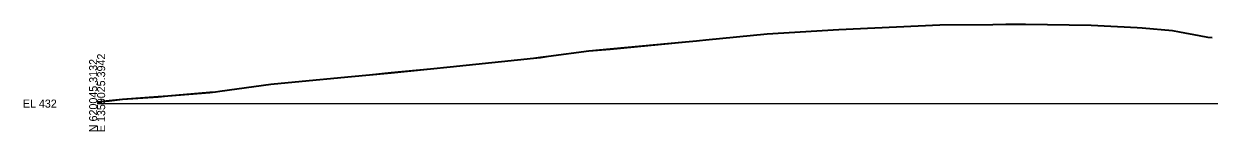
# Model space of a CAD drawing. Extents: x -26 to 803, y -27 to 3586.
# Drawn here: x -25.7 to 389.1, y 2990.3 to 3027.9 of the extents above; entities that cross this region are included whole.
import ezdxf

# ---------------------------------------------------------------- set-up
doc = ezdxf.new("R2010")
doc.units = 0
for name, color, linetype in [('DESIGN - SHEET - Light Grid', 7, 'Continuous'), ('SURVEY - GROUND - Bottom of Topsoil Layer', 7, 'Continuous'), ('SURVEY - GROUND - Top of Ground', 7, 'Continuous')]:
    doc.layers.add(name, color=color, linetype=linetype)

msp = doc.modelspace()

# ---------------------------------------------------------------- linework, layer by layer
at = {"layer": 'DESIGN - SHEET - Light Grid'}
msp.add_line((0, 3000), (400, 3000), dxfattribs=at)
at = {"layer": 'SURVEY - GROUND - Bottom of Topsoil Layer'}
for p, q in [((212.92, 3022.16), (234.42, 3024.27)), ((234.42, 3024.27), (259.53, 3025.76)), ((259.53, 3025.76), (272.12, 3026.35)), ((272.12, 3026.35), (294.85, 3027.45)), ((294.85, 3027.45), (313.39, 3027.55)), ((313.39, 3027.55), (317.86, 3027.61)), ((317.86, 3027.61), (320.11, 3027.67)), ((320.11, 3027.67), (321.84, 3027.69)), ((321.84, 3027.69), (324.75, 3027.61)), ((324.75, 3027.61), (347.82, 3027.26)), ((347.82, 3027.26), (363.88, 3026.5)), ((363.88, 3026.5), (365.66, 3026.4)), ((365.66, 3026.4), (376.24, 3025.47)), ((376.24, 3025.47), (378.72, 3025.01)), ((378.72, 3025.01), (385.5, 3023.66)), ((179.53, 3018.97), (205.87, 3021.45)), ((205.87, 3021.45), (209.66, 3021.81)), ((209.66, 3021.81), (210.76, 3021.92)), ((210.76, 3021.92), (212.92, 3022.16)), ((385.5, 3023.66), (388.58, 3023.15)), ((388.58, 3023.15), (390.12, 3022.95)), ((147.05, 3015.17), (152.71, 3015.79)), ((152.71, 3015.79), (155.06, 3016.06)), ((155.06, 3016.06), (157.88, 3016.43)), ((157.88, 3016.43), (172.02, 3018.29)), ((172.02, 3018.29), (179.53, 3018.97)), ((102.83, 3010.69), (116.65, 3012.03)), ((116.65, 3012.03), (123.48, 3012.72)), ((123.48, 3012.72), (147.05, 3015.17)), ((60.81, 3006.62), (69.23, 3007.47)), ((69.23, 3007.47), (88.95, 3009.34)), ((88.95, 3009.34), (95.26, 3009.91)), ((95.26, 3009.91), (102.83, 3010.69)), ((24.74, 3002.62), (39.41, 3003.81)), ((39.41, 3003.81), (41.46, 3004)), ((41.46, 3004), (42.9, 3004.2)), ((42.9, 3004.2), (60.81, 3006.62)), ((0, 3000.48), (4.26, 3000.89)), ((4.26, 3000.89), (8.89, 3001.41)), ((8.89, 3001.41), (21.33, 3002.3)), ((21.33, 3002.3), (24.74, 3002.62))]:
    msp.add_line(p, q, dxfattribs=at)
at = {"layer": 'SURVEY - GROUND - Top of Ground'}
msp.add_lwpolyline([(0, 3000.73), (4.26, 3001.14), (8.89, 3001.66), (21.33, 3002.55), (24.74, 3002.87), (39.41, 3004.06), (41.46, 3004.25), (42.9, 3004.45), (60.81, 3006.87), (69.23, 3007.72), (88.95, 3009.59), (95.26, 3010.16), (102.83, 3010.94), (116.65, 3012.28), (123.48, 3012.97), (147.05, 3015.42), (152.71, 3016.04), (155.06, 3016.31), (157.88, 3016.68), (172.02, 3018.54), (179.53, 3019.22), (205.87, 3021.7), (209.66, 3022.06), (210.76, 3022.17), (212.92, 3022.41), (234.42, 3024.52), (259.53, 3026.01), (272.12, 3026.6), (294.85, 3027.7), (313.39, 3027.8), (317.86, 3027.86), (320.11, 3027.92), (321.84, 3027.94), (324.75, 3027.86), (347.82, 3027.51), (363.88, 3026.75), (365.66, 3026.65), (376.24, 3025.72), (378.72, 3025.26), (385.5, 3023.91), (388.58, 3023.4), (390.12, 3023.2)], dxfattribs=at)

# ---------------------------------------------------------------- texts
at = {"layer": 'DESIGN - SHEET - Light Grid'}
for s, p in [('E 1359025.3942', (2.8, 2990)), ('N 620045.3132', (0, 2990))]:
    msp.add_text(s, height=2.8, rotation=90, dxfattribs=at).set_placement(p)
msp.add_text('EL 432', height=2.8, dxfattribs=at).set_placement((-26, 2998.6))

doc.saveas('drawing.dxf')
